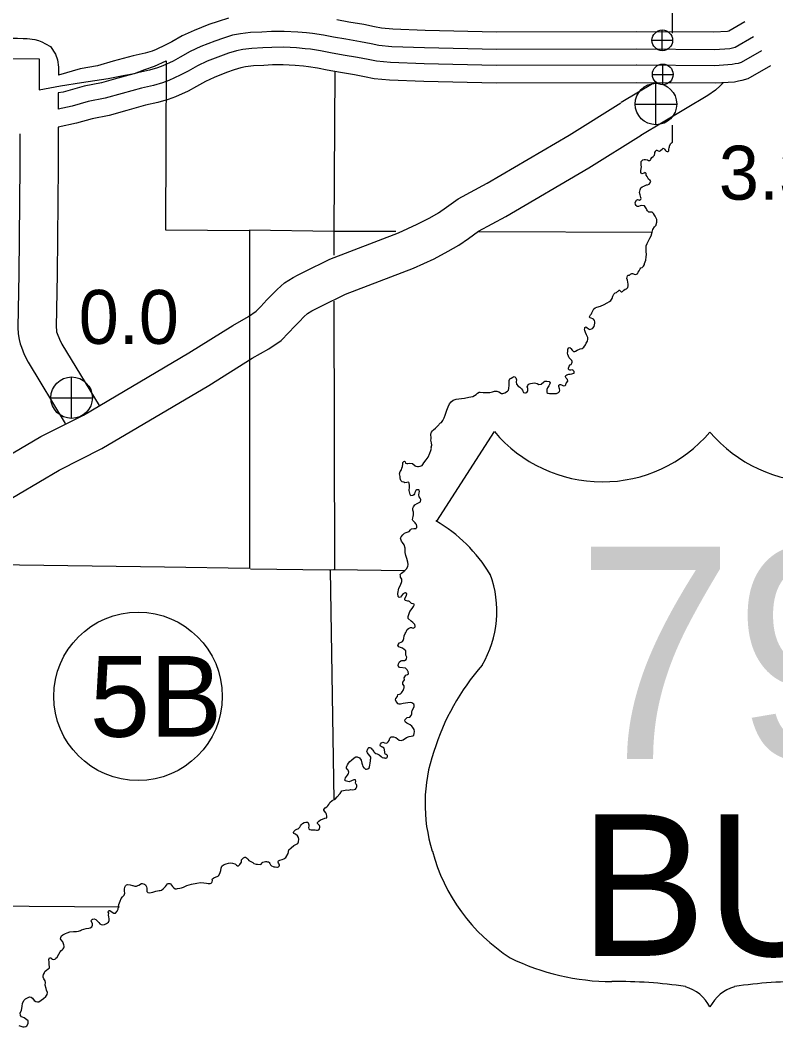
# Model space of a CAD drawing. Extents: x 369523 to 838377, y 495025 to 936819.
# Drawn here: x 723915 to 735755, y 626482 to 642261 of the extents above; entities that cross this region are included whole.
import ezdxf

# ---------------------------------------------------------------- set-up
doc = ezdxf.new("R2010")
doc.units = 0
for name, color, linetype in [('6', 7, 'Continuous'), ('DSN_BRDG_Annotation', 7, 'Continuous'), ('DSN_DRFT_Common-Annotations', 7, 'Continuous'), ('DSN_DRFT_Common-Line', 7, 'Continuous'), ('Level 1', 7, 'Continuous'), ('Level 11', 7, 'Continuous'), ('Level 15', 7, 'Continuous'), ('Level 2', 7, 'Continuous'), ('Level 22', 7, 'Continuous'), ('Level 6', 7, 'Continuous')]:
    doc.layers.add(name, color=color, linetype=linetype)

msp = doc.modelspace()

# ---------------------------------------------------------------- linework, layer by layer
at = {"layer": '6'}
msp.add_line((731344, 635812), (730436, 634406), dxfattribs=at)
for centre, radius, start, end in [((733037, 637235), 2211, 220.075, 319.6701), ((736408, 637235), 2211, 220.3299, 319.925), ((729248, 632366), 2361, 30.7809, 59.9883), ((729768, 632989), 1618, 328.8105, 21.2108), ((734000, 629672), 3776, 138.9565, 162.6913), ((732753, 629981), 2495, 160.9576, 197.3819), ((733160, 629988), 2887, 195.1074, 237.1312), ((733213, 630897), 3707, 244.0771, 269.5779), ((733299, 620402), 6790, 81.1942, 90.9539), ((734148, 626489), 651, 28.0342, 72.9864), ((735297, 626489), 651, 107.0136, 151.9658), ((736146, 620402), 6790, 89.0461, 98.8058)]:
    msp.add_arc(centre, radius, start, end, dxfattribs=at)
at = {"layer": 'DSN_DRFT_Common-Annotations'}
for p, q in [((733976, 641782), (733976, 642107)), ((733813, 641944), (734138, 641944)), ((733983, 641247), (733983, 641572)), ((733821, 641410), (734146, 641410)), ((733876, 640621), (733876, 641271)), ((733551, 640946), (734201, 640946)), ((724721, 636018), (724721, 636668)), ((724396, 636343), (725046, 636343))]:
    msp.add_line(p, q, dxfattribs=at)
for centre, radius in [((733976, 641944), 162), ((733983, 641410), 162), ((733876, 640946), 325), ((724721, 636343), 325)]:
    msp.add_circle(centre, radius, dxfattribs=at)
at = {"layer": 'DSN_DRFT_Common-Line'}
msp.add_circle((725762, 631662), 1320, dxfattribs=at)
at = {"layer": 'Level 1'}
for points in [[(722505, 641983), (722871, 641985), (723073, 641982), (723188, 641991), (723348, 641983), (723441, 641979), (723526, 641974), (723586, 641973), (723680, 641977), (723800, 641976), (723872, 641976), (723960, 641973), (724026, 641973), (724147, 641956), (724203, 641943), (724257, 641919), (724310, 641890), (724390, 641845), (724467, 641726), (724500, 641636), (724515, 641521), (724513, 641396)], [(723910, 640481), (723908, 639973), (723895, 638284), (723880, 637443), (723883, 637343), (723897, 637253), (723916, 637188), (723935, 637136), (723980, 637020), (724038, 636899), (724618, 635940)], [(724510, 640584), (724508, 639970), (724495, 638277), (724480, 637447), (724482, 637399), (724484, 637381), (724486, 637375), (724495, 637350), (724531, 637258), (724567, 637184), (725151, 636219)]]:
    msp.add_lwpolyline(points, dxfattribs=at)
at = {"layer": 'Level 11'}
msp.add_line((724512, 641119), (724511, 640866), dxfattribs=at)
for points in [[(727177, 642292), (727016, 642240), (726871, 642191), (726640, 642098), (726453, 642014), (726291, 641920), (726189, 641866), (726044, 641799), (725981, 641776), (725871, 641743), (725688, 641703), (725372, 641616), (725124, 641546), (724856, 641495), (724513, 641396)], [(733576, 642078), (731380, 642074), (730261, 642099), (729755, 642118), (729577, 642135), (729469, 642157), (729298, 642191), (729066, 642231), (728875, 642263)], [(735267, 642235), (735017, 642089), (734996, 642085), (734785, 642071), (733576, 642078)], [(733575, 641803), (731377, 641799), (730252, 641824), (729736, 641843), (729537, 641863), (729415, 641887), (729248, 641921), (729020, 641960), (728824, 641992), (728666, 642026), (728495, 642052), (728403, 642060), (728264, 642073), (728050, 642085), (727851, 642083), (727703, 642074), (727526, 642065), (727368, 642048), (727244, 642025), (727102, 641979), (726967, 641933), (726748, 641845), (726579, 641769), (726424, 641680), (726312, 641620), (726149, 641544), (726067, 641515), (725940, 641476), (725754, 641435), (725446, 641351), (725188, 641278), (724920, 641227), (724589, 641132), (724512, 641119)], [(735405, 641997), (735118, 641830), (735034, 641811), (734793, 641796), (733576, 641803)], [(733575, 641553), (731375, 641549), (730245, 641574), (729719, 641594), (729500, 641616), (729366, 641642), (729202, 641675), (728978, 641713), (728778, 641747), (728621, 641780), (728465, 641804), (728381, 641811), (728245, 641824), (728044, 641835), (727859, 641834), (727717, 641825), (727546, 641816), (727405, 641800), (727306, 641782), (727181, 641742), (727054, 641698), (726846, 641615), (726693, 641546), (726546, 641461), (726423, 641396), (726244, 641313), (726146, 641277), (726003, 641234), (725814, 641193), (725513, 641110), (725245, 641035), (724979, 640983), (724731, 640912), (724511, 640866)], [(735531, 641781), (735211, 641594), (735164, 641582), (735119, 641574), (735069, 641563), (734800, 641546), (733574, 641553)], [(733574, 641278), (731372, 641274), (730237, 641299), (729701, 641319), (729459, 641343), (729312, 641372), (729152, 641405), (728932, 641442), (728727, 641476), (728572, 641509), (728432, 641531), (728356, 641537), (728225, 641550), (728037, 641560), (727868, 641559), (727732, 641550), (727569, 641542), (727445, 641528), (727373, 641515), (727267, 641481), (727149, 641440), (726954, 641362), (726819, 641301), (726679, 641221), (726546, 641149), (726349, 641058), (726233, 641016), (726072, 640968), (725880, 640926), (725586, 640845), (725308, 640767), (725043, 640716), (724797, 640645), (724510, 640584)], [(735670, 641544), (735318, 641338), (735223, 641313), (735172, 641304), (735107, 641290), (734808, 641271), (733574, 641278)], [(733848, 641276), (733333, 640968)], [(734930, 641279), (734883, 641229), (734808, 641161), (734688, 641079), (733640, 640453)], [(723252, 635155), (724239, 635733), (724905, 636071), (726558, 637047), (727246, 637477), (727495, 637617), (727615, 637699), (727686, 637774), (727779, 637877), (727864, 637960), (727940, 638040), (728054, 638143), (728192, 638229), (728271, 638268), (728364, 638315), (728769, 638516), (729845, 638928), (730137, 639061), (730334, 639164), (730467, 639239), (730593, 639327), (730777, 639460), (731231, 639705), (732514, 640459), (733328, 640966)], [(723565, 634643), (724526, 635206), (725193, 635544), (726869, 636534), (727552, 636961), (727812, 637107), (728006, 637240), (728126, 637366), (728211, 637460), (728293, 637539), (728360, 637611), (728416, 637662), (728485, 637705), (728538, 637731), (728631, 637777), (729010, 637965), (730076, 638374), (730401, 638521), (730622, 638637), (730787, 638731), (730940, 638837), (731097, 638951), (731526, 639183), (732824, 639946), (733645, 640456)]]:
    msp.add_lwpolyline(points, dxfattribs=at)
at = {"layer": 'Level 15'}
msp.add_lwpolyline([(727523, 633662), (728756, 633643), (728826, 633651), (729947, 633633)], dxfattribs=at)
at = {"layer": 'Level 2'}
msp.add_lwpolyline([(723552, 641038), (723553, 641660), (724215, 641653), (724214, 641170), (724546, 641232), (724878, 641282), (725294, 641348), (725554, 641399), (725706, 641425), (725869, 641486), (726021, 641537), (726202, 641623), (726196, 640304), (726190, 638976), (727510, 638962), (727508, 636315), (727506, 633666), (726178, 633686), (723521, 633724), (723276, 633728), (722213, 633735)], dxfattribs=at)
at = {"layer": 'Level 22'}
for points in [[(728845, 641457), (728830, 638955), (728830, 638578)], [(727507, 638972), (728830, 638955), (729799, 638952)], [(731099, 638947), (733823, 638937)], [(728831, 637857), (728838, 633651)], [(728774, 633645), (728828, 630034)], [(718036, 628459), (723345, 628381), (725472, 628362)]]:
    msp.add_lwpolyline(points, dxfattribs=at)
at = {"layer": 'Level 6'}
for points in [[(734134, 642056), (734132, 644024), (734133, 644212)], [(733811, 640110), (733831, 640125), (733852, 640146), (733857, 640168), (733859, 640186), (733868, 640202), (733874, 640212), (733882, 640221), (733891, 640225), (733900, 640219), (733912, 640210), (733930, 640206), (733946, 640215), (733955, 640223), (733973, 640240), (733982, 640250), (733990, 640252), (734001, 640247), (734009, 640237), (734027, 640219), (734038, 640208), (734050, 640204), (734070, 640201), (734077, 640213), (734079, 640227), (734079, 640237), (734084, 640259), (734087, 640273), (734091, 640288), (734110, 640328), (734119, 640339), (734137, 640347), (734137, 640615)], [(733428, 638252), (733442, 638261), (733458, 638265), (733462, 638265), (733478, 638278), (733497, 638289), (733509, 638291), (733523, 638285), (733535, 638278), (733555, 638274), (733573, 638277), (733583, 638283), (733591, 638292), (733596, 638308), (733611, 638332), (733628, 638363), (733638, 638377), (733662, 638384), (733679, 638403), (733696, 638429), (733698, 638445), (733705, 638474), (733716, 638498), (733724, 638552), (733727, 638585), (733724, 638633), (733722, 638679), (733725, 638725), (733737, 638759), (733758, 638804), (733781, 638843), (733803, 638880), (733819, 638936), (733828, 638981), (733853, 639023), (733870, 639038), (733878, 639046), (733879, 639058), (733890, 639095), (733889, 639137), (733876, 639168), (733865, 639186), (733855, 639206), (733840, 639231), (733815, 639249), (733781, 639250), (733767, 639253), (733745, 639270), (733736, 639286), (733726, 639304), (733707, 639335), (733698, 639349), (733644, 639357), (733630, 639351), (733601, 639342), (733583, 639339), (733564, 639355), (733554, 639372), (733549, 639404), (733570, 639439), (733587, 639448), (733603, 639444), (733619, 639441), (733641, 639455), (733645, 639464), (733640, 639483), (733629, 639523), (733620, 639559), (733628, 639603), (733641, 639634), (733661, 639650), (733684, 639657), (733730, 639679), (733743, 639681), (733769, 639692), (733788, 639713), (733794, 639729), (733787, 639749), (733761, 639768), (733756, 639776), (733741, 639809), (733725, 639833), (733722, 639857), (733709, 639870), (733692, 639862), (733656, 639853), (733639, 639870), (733638, 639900), (733647, 639935), (733648, 639963), (733644, 639987), (733646, 640045), (733671, 640072), (733693, 640076), (733711, 640077), (733743, 640072), (733761, 640058), (733777, 640061), (733793, 640070), (733798, 640082), (733811, 640110)], [(732542, 636775), (732528, 636774), (732514, 636780), (732506, 636792), (732507, 636806), (732514, 636838), (732531, 636857), (732545, 636865), (732547, 636865), (732559, 636882), (732564, 636898), (732566, 636912), (732557, 636924), (732526, 636955), (732514, 636970), (732505, 636992), (732496, 637018), (732490, 637042), (732489, 637050), (732497, 637064), (732498, 637082), (732498, 637102), (732509, 637126), (732525, 637129), (732543, 637113), (732566, 637088), (732586, 637069), (732603, 637065), (732618, 637072), (732642, 637089), (732681, 637106), (732691, 637108), (732721, 637115), (732748, 637134), (732771, 637171), (732784, 637199), (732803, 637228), (732808, 637260), (732807, 637288), (732790, 637330), (732770, 637367), (732762, 637395), (732759, 637409), (732762, 637429), (732764, 637441), (732780, 637452), (732796, 637444), (732817, 637421), (732843, 637414), (732867, 637421), (732884, 637429), (732888, 637431), (732907, 637458), (732916, 637486), (732921, 637512), (732919, 637534), (732912, 637554), (732896, 637572), (732887, 637581), (732861, 637589), (732843, 637594), (732836, 637608), (732842, 637620), (732851, 637644), (732865, 637659), (732874, 637673), (732889, 637706), (732904, 637734), (732924, 637751), (732951, 637762), (733009, 637778), (733064, 637804), (733111, 637831), (733146, 637850), (733167, 637867), (733192, 637900), (733203, 637934), (733218, 637967), (733239, 637986), (733257, 637994), (733273, 638005), (733284, 638013), (733298, 638030), (733310, 638028), (733316, 638018), (733319, 638010), (733331, 638001), (733341, 638003), (733351, 638005), (733360, 638014), (733374, 638028), (733393, 638045), (733413, 638051), (733434, 638070), (733441, 638098), (733441, 638124), (733436, 638154), (733431, 638186), (733422, 638212), (733423, 638230), (733428, 638252)], [(731008, 636360), (731057, 636392), (731081, 636415), (731108, 636428), (731120, 636430), (731170, 636422), (731216, 636423), (731244, 636424), (731272, 636425), (731318, 636435), (731349, 636444), (731385, 636447), (731413, 636436), (731456, 636409), (731478, 636408), (731508, 636419), (731549, 636444), (731566, 636463), (731571, 636487), (731578, 636539), (731574, 636587), (731575, 636613), (731588, 636638), (731606, 636650), (731635, 636667), (731653, 636674), (731663, 636672), (731682, 636653), (731689, 636621), (731688, 636589), (731693, 636553), (731718, 636524), (731744, 636506), (731771, 636483), (731786, 636462), (731792, 636444), (731803, 636426), (731821, 636417), (731835, 636419), (731851, 636426), (731862, 636442), (731868, 636454), (731867, 636488), (731860, 636512), (731867, 636530), (731875, 636549), (731892, 636559), (731910, 636566), (731944, 636573), (731976, 636576), (732014, 636567), (732040, 636552), (732078, 636555), (732119, 636589), (732137, 636601), (732166, 636602), (732201, 636595), (732217, 636578), (732216, 636560), (732199, 636531), (732176, 636498), (732165, 636472), (732168, 636426), (732183, 636414), (732209, 636409), (732281, 636406), (732320, 636411), (732350, 636426), (732365, 636438), (732371, 636461), (732366, 636483), (732357, 636518), (732356, 636540), (732372, 636549), (732382, 636549), (732394, 636544), (732406, 636540), (732430, 636531), (732452, 636533), (732464, 636546), (732471, 636568), (732475, 636578), (732494, 636601), (732489, 636627), (732472, 636648), (732458, 636672), (732457, 636680), (732465, 636690), (732481, 636701), (732494, 636707), (732512, 636710), (732530, 636712), (732556, 636719), (732576, 636724), (732596, 636726), (732595, 636746), (732593, 636754), (732586, 636762), (732582, 636768), (732562, 636777), (732542, 636775)], [(730063, 634428), (730066, 634460), (730071, 634481), (730077, 634507), (730077, 634549), (730068, 634581), (730069, 634613), (730078, 634633), (730099, 634662), (730137, 634683), (730186, 634713), (730192, 634747), (730182, 634769), (730169, 634790), (730160, 634822), (730169, 634852), (730170, 634874), (730168, 634892), (730162, 634900), (730150, 634900), (730130, 634899), (730116, 634889), (730101, 634858), (730092, 634838), (730082, 634822), (730067, 634809), (730035, 634804), (730024, 634828), (730012, 634887), (730013, 634939), (730014, 634958), (730014, 634966), (730011, 635002), (730006, 635015), (729992, 635017), (729972, 635012), (729940, 635011), (729924, 635017), (729902, 635022), (729879, 635043), (729875, 635059), (729870, 635087), (729867, 635109), (729856, 635149), (729869, 635187), (729888, 635214), (729897, 635240), (729906, 635267), (729909, 635303), (729912, 635325), (729926, 635341), (729939, 635348), (729946, 635338), (729952, 635316), (729973, 635311), (729991, 635311), (730018, 635318), (730060, 635312), (730103, 635275), (730116, 635269), (730140, 635266), (730154, 635267), (730184, 635268), (730211, 635279), (730225, 635295), (730238, 635321), (730274, 635367), (730305, 635410), (730331, 635471), (730347, 635515), (730358, 635554), (730357, 635568), (730364, 635598), (730361, 635636), (730350, 635678), (730355, 635698), (730357, 635712), (730351, 635764), (730349, 635774), (730352, 635788), (730358, 635804), (730373, 635823), (730393, 635837), (730420, 635864), (730453, 635894), (730503, 635947), (730515, 635954), (730538, 635986), (730560, 636029), (730575, 636068), (730602, 636145), (730623, 636198), (730641, 636246), (730666, 636277), (730701, 636304), (730748, 636320), (730828, 636330), (730875, 636338), (730945, 636352), (730975, 636355), (731008, 636360)], [(729968, 632255), (729971, 632277), (729958, 632307), (729959, 632353), (729960, 632373), (729931, 632398), (729905, 632415), (729872, 632430), (729846, 632439), (729833, 632463), (729835, 632477), (729860, 632500), (729882, 632511), (729907, 632519), (729915, 632536), (729926, 632566), (729934, 632609), (729947, 632645), (729957, 632663), (729970, 632686), (729981, 632710), (730000, 632727), (730018, 632737), (730032, 632740), (730046, 632740), (730058, 632737), (730074, 632731), (730094, 632742), (730103, 632754), (730103, 632764), (730096, 632788), (730080, 632808), (730069, 632817), (730039, 632840), (729995, 632881), (729996, 632915), (730022, 632992), (730058, 633039), (730079, 633068), (730094, 633103), (730072, 633112), (730046, 633119), (730017, 633148), (730007, 633154), (729989, 633153), (729952, 633166), (729940, 633174), (729941, 633196), (729966, 633243), (729971, 633269), (729952, 633286), (729933, 633280), (729919, 633269), (729907, 633257), (729892, 633236), (729875, 633218), (729853, 633213), (729839, 633227), (729833, 633272), (729850, 633355), (729875, 633404), (729893, 633463), (729894, 633497), (729875, 633532), (729872, 633550), (729869, 633570), (729892, 633595), (729933, 633624), (729970, 633662), (729987, 633696), (729992, 633727), (729989, 633766), (729975, 633820), (729956, 633868), (729948, 633915), (729948, 633966), (729946, 633985), (729932, 634039), (729907, 634072), (729888, 634094), (729875, 634139), (729882, 634160), (729909, 634191), (729936, 634218), (729964, 634231), (730009, 634246), (730032, 634271), (730048, 634285), (730081, 634292), (730099, 634295), (730117, 634294), (730117, 634296), (730129, 634308), (730132, 634320), (730132, 634330), (730127, 634354), (730121, 634360), (730113, 634368), (730102, 634383), (730065, 634418), (730063, 634428)], [(729669, 630712), (729672, 630722), (729670, 630734), (729653, 630748), (729639, 630753), (729631, 630769), (729626, 630787), (729621, 630825), (729618, 630849), (729594, 630864), (729578, 630870), (729559, 630879), (729557, 630895), (729557, 630903), (729558, 630913), (729578, 630934), (729599, 630942), (729625, 630935), (729648, 630930), (729663, 630931), (729683, 630947), (729698, 630970), (729707, 631004), (729730, 631025), (729762, 631026), (729800, 631015), (729827, 630998), (729854, 630973), (729886, 630972), (729915, 630981), (729968, 631015), (730010, 631032), (730043, 631039), (730067, 631044), (730085, 631054), (730090, 631081), (730093, 631109), (730086, 631143), (730069, 631172), (730054, 631192), (730024, 631215), (729993, 631232), (729971, 631243), (729950, 631256), (729942, 631278), (729949, 631298), (729963, 631313), (729980, 631328), (730016, 631335), (730020, 631337), (730039, 631360), (730052, 631390), (730051, 631414), (730058, 631442), (730079, 631475), (730090, 631501), (730089, 631523), (730083, 631539), (730052, 631562), (730028, 631566), (729953, 631555), (729915, 631550), (729875, 631541), (729851, 631540), (729837, 631547), (729806, 631582), (729797, 631608), (729799, 631630), (729825, 631661), (729830, 631691), (729856, 631696), (729872, 631701), (729890, 631715), (729899, 631734), (729914, 631754), (729925, 631783), (729933, 631797), (729932, 631829), (729913, 631854), (729909, 631868), (729910, 631886), (729925, 631905), (729935, 631923), (729934, 631953), (729958, 631992), (729982, 632005), (729998, 632017), (729995, 632049), (729988, 632057), (729978, 632077), (729951, 632102), (729865, 632115), (729850, 632121), (729840, 632147), (729843, 632169), (729860, 632201), (729881, 632218), (729895, 632224), (729937, 632226), (729962, 632237), (729968, 632255)], [(728720, 629786), (728714, 629814), (728703, 629837), (728682, 629861), (728672, 629878), (728675, 629891), (728692, 629913), (728722, 629932), (728733, 629947), (728749, 629965), (728768, 629998), (728802, 630031), (728848, 630050), (728882, 630086), (728925, 630133), (728929, 630139), (728957, 630180), (729033, 630195), (729059, 630194), (729098, 630201), (729116, 630197), (729148, 630200), (729170, 630209), (729181, 630222), (729189, 630246), (729190, 630262), (729186, 630278), (729173, 630289), (729169, 630303), (729172, 630334), (729169, 630351), (729143, 630353), (729104, 630337), (729072, 630324), (729026, 630331), (729006, 630340), (729002, 630352), (729005, 630366), (729014, 630387), (729041, 630425), (729055, 630442), (729060, 630454), (729062, 630472), (729055, 630504), (729038, 630522), (729027, 630537), (729029, 630551), (729033, 630565), (729044, 630590), (729057, 630616), (729082, 630643), (729105, 630664), (729150, 630699), (729173, 630714), (729197, 630715), (729230, 630700), (729257, 630661), (729270, 630617), (729277, 630585), (729286, 630560), (729297, 630542), (729309, 630534), (729325, 630521), (729343, 630521), (729363, 630526), (729381, 630541), (729388, 630559), (729395, 630583), (729398, 630615), (729403, 630652), (729406, 630672), (729410, 630690), (729407, 630708), (729401, 630726), (729366, 630763), (729357, 630776), (729348, 630802), (729355, 630826), (729367, 630849), (729374, 630857), (729380, 630859), (729392, 630860), (729415, 630852), (729427, 630835), (729437, 630821), (729454, 630800), (729463, 630786), (729485, 630766), (729507, 630759), (729540, 630744), (729571, 630717), (729579, 630711), (729589, 630706), (729611, 630700), (729629, 630697), (729639, 630695), (729643, 630695), (729653, 630696), (729659, 630700), (729665, 630708), (729669, 630712)], [(727358, 629026), (727382, 629065), (727385, 629097), (727395, 629110), (727405, 629122), (727416, 629130), (727434, 629139), (727438, 629139), (727444, 629139), (727460, 629132), (727481, 629108), (727499, 629091), (727518, 629080), (727558, 629059), (727575, 629043), (727613, 629029), (727635, 629029), (727673, 629027), (727691, 629033), (727704, 629052), (727716, 629062), (727759, 629073), (727777, 629072), (727790, 629070), (727804, 629067), (727814, 629059), (727826, 629040), (727839, 629022), (727855, 629006), (727878, 628993), (727890, 628991), (727912, 628988), (727934, 628987), (727948, 628987), (727962, 628990), (727973, 629002), (727977, 629014), (727977, 629020), (727972, 629034), (727964, 629046), (727955, 629064), (727957, 629074), (727965, 629084), (727984, 629093), (728018, 629104), (728046, 629115), (728077, 629136), (728113, 629199), (728123, 629256), (728160, 629289), (728203, 629322), (728234, 629339), (728263, 629358), (728274, 629383), (728283, 629423), (728278, 629447), (728261, 629476), (728229, 629501), (728212, 629509), (728202, 629513), (728198, 629526), (728203, 629543), (728213, 629555), (728229, 629568), (728248, 629578), (728266, 629583), (728270, 629585), (728287, 629599), (728297, 629612), (728308, 629630), (728316, 629647), (728327, 629661), (728341, 629671), (728364, 629684), (728392, 629691), (728420, 629692), (728429, 629678), (728439, 629649), (728436, 629626), (728435, 629604), (728440, 629584), (728454, 629577), (728476, 629570), (728506, 629571), (728538, 629570), (728556, 629564), (728576, 629565), (728594, 629571), (728603, 629586), (728610, 629608), (728610, 629624), (728604, 629636), (728595, 629650), (728573, 629667), (728574, 629687), (728595, 629706), (728621, 629729), (728650, 629739), (728686, 629751), (728719, 629760), (728720, 629786)], [(725307, 628176), (725306, 628204), (725301, 628232), (725302, 628266), (725294, 628280), (725297, 628296), (725307, 628303), (725321, 628307), (725342, 628290), (725380, 628265), (725384, 628263), (725408, 628266), (725437, 628293), (725448, 628325), (725462, 628398), (725480, 628451), (725495, 628491), (725516, 628520), (725543, 628545), (725556, 628577), (725551, 628609), (725552, 628639), (725557, 628669), (725564, 628690), (725581, 628710), (725597, 628713), (725637, 628706), (725674, 628697), (725680, 628695), (725696, 628690), (725712, 628686), (725736, 628687), (725758, 628696), (725773, 628704), (725814, 628726), (725828, 628726), (725861, 628717), (725877, 628706), (725892, 628678), (725899, 628656), (725899, 628632), (725898, 628616), (725902, 628604), (725915, 628585), (725939, 628584), (725992, 628593), (726040, 628609), (726066, 628616), (726095, 628617), (726111, 628617), (726127, 628622), (726154, 628643), (726193, 628682), (726224, 628725), (726236, 628727), (726242, 628728), (726262, 628728), (726270, 628723), (726286, 628703), (726303, 628682), (726316, 628664), (726342, 628647), (726364, 628647), (726382, 628652), (726418, 628657), (726443, 628660), (726475, 628671), (726493, 628682), (726528, 628695), (726601, 628719), (726681, 628732), (726742, 628742), (726790, 628739), (726836, 628735), (726862, 628730), (726892, 628729), (726910, 628733), (726918, 628742), (726923, 628756), (726927, 628776), (726922, 628794), (726947, 628815), (726961, 628821), (727001, 628836), (727024, 628849), (727043, 628884), (727059, 628931), (727064, 628969), (727077, 629001), (727102, 629020), (727142, 629035), (727179, 629047), (727215, 629052), (727243, 629049), (727276, 629038), (727288, 629032), (727306, 629015), (727322, 629007), (727336, 629008), (727348, 629014), (727358, 629026)], [(724005, 626487), (724018, 626496), (724039, 626532), (724040, 626578), (723999, 626609), (723976, 626624), (723954, 626634), (723936, 626641), (723919, 626661), (723916, 626699), (723935, 626739), (723946, 626804), (723951, 626848), (723973, 626895), (723999, 626920), (724050, 626949), (724067, 626954), (724085, 626949), (724106, 626929), (724133, 626894), (724158, 626881), (724186, 626874), (724208, 626876), (724245, 626900), (724278, 626927), (724315, 626958), (724338, 626987), (724343, 627021), (724325, 627059), (724321, 627082), (724309, 627134), (724312, 627176), (724307, 627202), (724286, 627234), (724275, 627259), (724274, 627275), (724278, 627303), (724289, 627320), (724302, 627348), (724331, 627373), (724349, 627384), (724374, 627409), (724376, 627421), (724370, 627461), (724367, 627495), (724362, 627535), (724373, 627561), (724385, 627565), (724393, 627562), (724405, 627552), (724420, 627542), (724438, 627539), (724459, 627542), (724467, 627548), (724475, 627556), (724494, 627575), (724519, 627622), (724540, 627659), (724553, 627675), (724576, 627692), (724588, 627702), (724599, 627719), (724605, 627733), (724605, 627745), (724600, 627769), (724582, 627812), (724555, 627845), (724549, 627859), (724550, 627883), (724561, 627906), (724581, 627926), (724624, 627946), (724652, 627957), (724693, 627970), (724751, 627978), (724797, 627978), (724830, 627983), (724862, 627994), (724878, 628000), (724947, 628022), (724991, 628026), (725012, 628033), (725036, 628049), (725047, 628074), (725048, 628100), (725029, 628139), (725033, 628153), (725046, 628168), (725054, 628170), (725076, 628175), (725102, 628164), (725118, 628150), (725145, 628117), (725162, 628098), (725182, 628088), (725210, 628083), (725236, 628086), (725270, 628099), (725297, 628120), (725308, 628148), (725307, 628176)], [(723894, 626504), (723927, 626495), (723957, 626482), (723979, 626482), (724005, 626487)]]:
    msp.add_lwpolyline(points, dxfattribs=at)

# ---------------------------------------------------------------- texts
at = {"layer": '6'}
for s, height, p in [('79', 3326.4, (732631, 630679)), ('BUS', 2217.6, (732682, 627594))]:
    msp.add_text(s, height=height, dxfattribs=at).set_placement(p)
at = {"layer": 'DSN_BRDG_Annotation'}
for s, p in [('3.32 CO. LINE', (734862, 639447)), ('0.0', (724832, 637187))]:
    msp.add_text(s, height=844.8, dxfattribs=at).set_placement(p)
at = {"layer": 'DSN_DRFT_Common-Line'}
msp.add_text('5B', height=1267.2, dxfattribs=at).set_placement((725006, 631028))

doc.saveas('drawing.dxf')
